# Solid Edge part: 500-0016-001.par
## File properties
Title: 500-0016-00.par
Author: James M. Robinson
Template: NORMAL.PAR
Last saved by: jccrumbl
Revision: 50
Application: Solid Edge
Revision: A
Teamcenter Item Type: Item
Accuracy: 0.99
TC_ImportTime: 2008-07-08
PartType: -
Last Saved Version: -
File Size: 0
Number of Sheets: 0
Number of Objects: 0
Material: aluminum
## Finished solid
Body 1: solid body, 20 faces, 36 edges, 18 vertices.
  Faces by surface: plane 16, cylinder 2, cone 1, torus 1
  Edges by curve: line 30, circle 6
Bounding box of the edges (mm; curved faces can reach further): 13.000 x 33.000 x 13.000, from (-6.5, -8, -6.5) to (6.5, 25, 6.5).
Cylindrical faces by radius (mm): R4 x1, R6.5 x1
Conical faces (half-angle, radius in mm at the cone's reference point): 45 deg R3.375 x1
Toroidal faces (ring radius, tube radius in mm): R6 r0.5 x1
Planar faces by outward normal: +y 2, +z 1, -y 2, -z 1, oblique 10
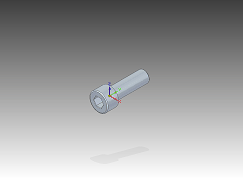
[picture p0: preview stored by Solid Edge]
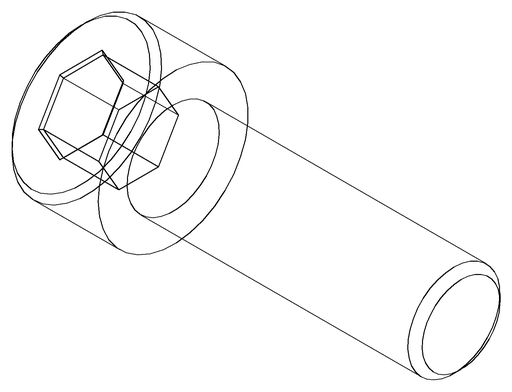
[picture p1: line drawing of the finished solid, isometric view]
